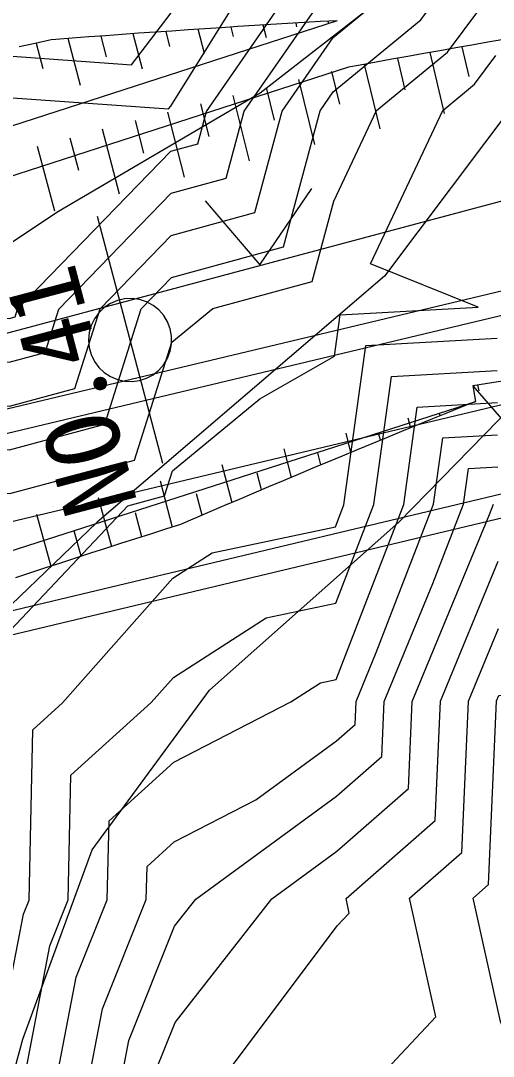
# Model space of a CAD drawing. Extents: x 42655 to 43811, y -141820 to -141156.
# Drawn here: x 43266.1 to 43280.88, y -141374.58 to -141342.18 of the extents above; entities that cross this region are included whole.
import ezdxf

# ---------------------------------------------------------------- set-up
doc = ezdxf.new("R2010")
doc.units = 0
for name, color, linetype in [('D-BMK-HTXT_1', 7, 'Continuous'), ('D-BMK_1', 7, 'Continuous'), ('D-STR-STR4_1', 7, 'Continuous'), ('D-STR-STR5_1', 7, 'Continuous'), ('D-STR_1', 7, 'Continuous'), ('ZE_HICN', 7, 'Continuous'), ('ZE_LWCN', 7, 'Continuous'), ('地形', 7, 'Continuous')]:
    doc.layers.add(name, color=color, linetype=linetype)

msp = doc.modelspace()

# ---------------------------------------------------------------- linework, layer by layer
at = {"layer": 'D-BMK-HTXT_1'}
msp.add_line((43270.542, -141356.034), (43268.499, -141348.3), dxfattribs=at)
msp.add_lwpolyline([(43268.22, -141352.167), (43268.241, -141352.399), (43268.303, -141352.624), (43268.404, -141352.834), (43268.541, -141353.022), (43268.71, -141353.183), (43268.904, -141353.312), (43269.119, -141353.403), (43269.346, -141353.455), (43269.579, -141353.466), (43269.81, -141353.434), (43270.031, -141353.362), (43270.237, -141353.252), (43270.419, -141353.107), (43270.572, -141352.931), (43270.692, -141352.731), (43270.774, -141352.513), (43270.815, -141352.284), (43270.815, -141352.05), (43270.774, -141351.821), (43270.692, -141351.603), (43270.572, -141351.403), (43270.419, -141351.227), (43270.237, -141351.082), (43270.031, -141350.972), (43269.81, -141350.9), (43269.579, -141350.868), (43269.346, -141350.879), (43269.119, -141350.931), (43268.904, -141351.022), (43268.71, -141351.151), (43268.541, -141351.312), (43268.404, -141351.5), (43268.303, -141351.71), (43268.241, -141351.935), (43268.22, -141352.167)], dxfattribs=at)
at = {"layer": 'D-BMK_1'}
msp.add_lwpolyline([(43339.878, -141340.165), (43219.961, -141368.793)], dxfattribs=at)
at = {"layer": 'D-STR-STR4_1'}
for p, q in [((43280.239, -141353.603), (43282.194, -141355.865)), ((43280.384, -141353.565), (43280.429, -141353.753))]:
    msp.add_line(p, q, dxfattribs=at)
at = {"layer": 'D-STR-STR5_1'}
for p, q in [((43272.666, -141342.375), (43272.739, -141342.666)), ((43273.782, -141342.716), (43273.682, -141342.311)), ((43274.697, -141342.25), (43274.725, -141342.364)), ((43275.724, -141342.241), (43275.713, -141342.192)), ((43267.968, -141344.198), (43267.583, -141342.733)), ((43268.6, -141342.656), (43268.768, -141343.301)), ((43269.903, -141343.695), (43269.617, -141342.582)), ((43270.633, -141342.511), (43270.753, -141342.979)), ((43271.841, -141343.201), (43271.65, -141342.442)), ((43266.582, -141342.878), (43266.792, -141343.666)), ((43279.896, -141342.993), (43280.111, -141343.922)), ((43277.879, -141343.353), (43278.111, -141344.334)), ((43279.353, -141345.078), (43278.905, -141343.169)), ((43277.336, -141345.556), (43276.853, -141343.541)), ((43275.295, -141346.051), (43274.795, -141344.011)), ((43275.82, -141343.761), (43276.068, -141344.782)), ((43273.77, -141344.264), (43274.023, -141345.283)), ((43273.257, -141346.557), (43272.746, -141344.52)), ((43271.723, -141344.778), (43271.981, -141345.796)), ((43269.678, -141345.302), (43269.941, -141346.319)), ((43271.222, -141347.073), (43270.7, -141345.039)), ((43269.189, -141347.6), (43268.657, -141345.568)), ((43267.636, -141345.837), (43267.905, -141346.852)), ((43267.159, -141348.137), (43266.616, -141346.109)), ((43280.151, -141354.134), (43280.157, -141354.159)), ((43278.207, -141354.602), (43278.284, -141354.919)), ((43279.22, -141354.538), (43279.199, -141354.452)), ((43277.349, -141355.302), (43277.292, -141355.071)), ((43276.265, -141355.08), (43276.416, -141355.688)), ((43274.325, -141355.568), (43274.553, -141356.466)), ((43275.484, -141356.076), (43275.389, -141355.699)), ((43272.388, -141356.065), (43272.696, -141357.253)), ((43273.624, -141356.858), (43273.49, -141356.337)), ((43270.453, -141356.572), (43270.837, -141358.021)), ((43271.77, -141357.65), (43271.595, -141356.984)), ((43268.521, -141357.09), (43268.937, -141358.627)), ((43266.592, -141357.616), (43267.04, -141359.241)), ((43269.887, -141358.323), (43269.687, -141357.576)), ((43267.988, -141358.933), (43267.772, -141358.142))]:
    msp.add_line(p, q, dxfattribs=at)
for points in [[(43275.994, -141342.176), (43216.96, -141361.274)], [(43275.994, -141342.176), (43275.476, -141342.205), (43274.959, -141342.235), (43274.442, -141342.265), (43273.924, -141342.297), (43273.407, -141342.328), (43272.889, -141342.361), (43272.372, -141342.394), (43271.854, -141342.428), (43271.336, -141342.463), (43270.818, -141342.498), (43270.3, -141342.534), (43269.782, -141342.57), (43269.264, -141342.608), (43268.746, -141342.645), (43268.228, -141342.684), (43267.71, -141342.723), (43267.191, -141342.763), (43267.05, -141342.774), (43266.55, -141342.885), (43266.05, -141342.996)], [(43281.211, -141342.764), (43280.711, -141342.851), (43280.21, -141342.938), (43279.71, -141343.026), (43279.209, -141343.115), (43278.709, -141343.204), (43278.209, -141343.294), (43277.709, -141343.384), (43277.209, -141343.475), (43276.709, -141343.567), (43276.345, -141343.634)], [(43276.345, -141343.634), (43217.529, -141362.662)], [(43280.32, -141354.094), (43279.855, -141354.281), (43279.391, -141354.468), (43278.928, -141354.656), (43278.465, -141354.845), (43278.002, -141355.034), (43277.539, -141355.224), (43277.077, -141355.415), (43276.615, -141355.605), (43276.153, -141355.797), (43275.692, -141355.989), (43275.231, -141356.181), (43274.77, -141356.375), (43274.31, -141356.568), (43273.85, -141356.763), (43273.39, -141356.957), (43272.931, -141357.153), (43272.472, -141357.349), (43272.013, -141357.545), (43271.555, -141357.742), (43271.097, -141357.939), (43270.626, -141358.088), (43270.156, -141358.237), (43269.685, -141358.387), (43269.215, -141358.537), (43268.745, -141358.688), (43268.276, -141358.84), (43267.806, -141358.992), (43267.337, -141359.145), (43266.868, -141359.298), (43266.399, -141359.452), (43265.93, -141359.606)]]:
    msp.add_lwpolyline(points, dxfattribs=at)
at = {"layer": 'D-STR_1'}
msp.add_line((43280.239, -141353.603), (43280.32, -141354.094), dxfattribs=at)
for points in [[(43339.6, -141336.676), (43218.633, -141365.555)], [(43339.659, -141337.424), (43218.917, -141366.249)], [(43317.868, -141337.995), (43218.254, -141364.63)], [(43340.097, -141342.907), (43221.004, -141371.338)], [(43340.157, -141343.654), (43221.288, -141372.032)], [(43340.196, -141344.153), (43280.239, -141353.603)], [(43280.321, -141354.098), (43221.668, -141372.957)]]:
    msp.add_lwpolyline(points, dxfattribs=at)
at = {"layer": 'ZE_HICN'}
for points in [[(43249.689, -141374.859), (43250.57, -141373.588), (43252.624, -141369.757), (43253.076, -141366.667), (43253.74, -141363.589), (43254.854, -141358.308), (43255.054, -141357.42), (43255.176, -141356.93), (43255.574, -141355.76), (43257.228, -141351.247), (43258.712, -141348.917), (43260.625, -141347.681), (43263.355, -141345.055), (43264.697, -141343.841), (43265.692, -141343.273), (43269.564, -141343.552), (43270.774, -141341.968), (43272.722, -141338.849), (43274.151, -141336.8), (43275.833, -141335.898), (43278.271, -141332.66), (43277.915, -141330.107), (43278.412, -141326.496), (43276.737, -141321.518)], [(43255.992, -141375.904), (43258.278, -141372.907), (43260.154, -141369.721), (43260.702, -141364.205), (43260.778, -141363.65), (43260.782, -141363.556), (43260.851, -141363.37), (43263.775, -141357.379), (43264.16, -141355.452), (43265.75, -141355.603), (43268.727, -141354.803), (43269.864, -141351.187), (43270.813, -141350.209), (43274.319, -141349.256), (43275.461, -141344.998), (43275.874, -141344.402), (43278.608, -141342.146), (43280.936, -141339.002)], [(43267.112, -141375.851), (43267.827, -141372.107), (43268.801, -141369.681), (43268.858, -141367.215), (43270.884, -141365.379), (43274.545, -141363.491), (43275.472, -141362.895), (43275.96, -141362.791), (43278.076, -141357.311), (43278.496, -141354.267), (43281.007, -141354.126)], [(43276.773, -141375.806), (43279.079, -141373.349), (43278.258, -141369.636), (43279.895, -141368.201), (43280.102, -141363.465), (43281.041, -141361.189)]]:
    msp.add_lwpolyline(points, dxfattribs=at)
at = {"layer": 'ZE_LWCN'}
for points in [[(43250.656, -141375.837), (43253.918, -141369.751), (43254.177, -141367.987), (43255.126, -141363.582), (43255.601, -141361.333), (43256.265, -141358.237), (43256.781, -141357.412), (43257.326, -141355.285), (43258.808, -141351.24), (43259.605, -141349.988), (43260.632, -141349.325), (43265.079, -141345.047), (43265.435, -141344.726), (43265.698, -141344.575), (43270.719, -141344.937), (43270.787, -141344.848), (43274.539, -141338.84), (43275.137, -141337.982), (43275.841, -141337.605), (43279.569, -141332.654), (43279.024, -141328.751), (43279.335, -141326.492), (43278.288, -141323.378)], [(43253.251, -141375.916), (43255.648, -141371.394), (43256.302, -141370.537), (43256.773, -141369.737), (43256.929, -141368.166), (43257.937, -141363.569), (43258.505, -141360.923), (43260.671, -141357.456), (43260.701, -141357.393), (43261.682, -141352.479), (43265.737, -141352.864), (43266.859, -141352.562), (43267.288, -141351.2), (43270.8, -141347.575), (43272.527, -141347.106), (43273.089, -141345.01), (43275.858, -141341.007), (43276.925, -141340.126), (43277.889, -141338.824), (43280.916, -141334.723)], [(43254.572, -141375.91), (43255.66, -141373.859), (43257.29, -141371.722), (43258.463, -141369.729), (43258.853, -141365.814), (43259.346, -141363.562), (43259.624, -141362.267), (43260.685, -141360.568), (43262.238, -141357.386), (43262.921, -141353.966), (43265.744, -141354.233), (43267.793, -141353.683), (43268.576, -141351.194), (43270.807, -141348.892), (43273.423, -141348.181), (43274.275, -141345.004), (43275.866, -141342.705), (43277.766, -141341.136), (43279.484, -141338.817), (43280.926, -141336.863)], [(43251.929, -141375.923), (43254.404, -141371.255), (43255.213, -141369.745), (43255.277, -141369.307), (43255.631, -141367.667), (43256.527, -141363.576), (43257.385, -141359.58), (43258.745, -141357.403), (43260.184, -141351.79), (43260.388, -141351.232), (43260.498, -141351.06), (43260.64, -141350.968), (43261.653, -141349.994), (43262.841, -141351.221), (43265.731, -141351.495), (43265.925, -141351.442), (43266, -141351.206), (43270.794, -141346.258), (43271.631, -141346.031), (43271.903, -141345.015), (43275.85, -141339.309)], [(43257.891, -141375.895), (43259.266, -141374.092), (43260.737, -141371.593), (43262.241, -141369.711), (43262.746, -141366.011), (43262.85, -141363.546), (43264.655, -141358.718), (43265.313, -141357.372), (43265.399, -141356.938), (43265.756, -141356.972), (43269.66, -141355.923), (43270.822, -141352.23), (43272.102, -141351.177), (43275.215, -141350.331), (43275.89, -141347.817), (43277.226, -141344.99), (43279.449, -141343.155), (43280.946, -141341.134)], [(43282.012, -141375.781), (43281.099, -141373.486), (43280.246, -141369.627), (43280.73, -141369.202), (43280.981, -141363.46), (43281.051, -141363.292), (43285.524, -141362.697), (43285.017, -141357.279), (43284.951, -141352.493), (43285.655, -141351.113), (43285.616, -141350.553), (43286.078, -141350.476), (43289.935, -141349.606), (43291.16, -141349.042), (43295.511, -141344.904), (43295.716, -141344.286), (43296.225, -141344.098), (43300.912, -141344.391), (43301.314, -141344.304), (43301.911, -141344.15), (43306.395, -141342.794), (43309.436, -141342.362), (43311.48, -141342.159), (43313.792, -141341.46)], [(43260.254, -141375.277), (43260.751, -141374.433), (43264.533, -141369.701), (43264.714, -141368.372), (43264.919, -141363.536), (43265.777, -141361.242), (43269.445, -141357.352), (43270.594, -141357.043), (43270.841, -141356.258), (43273.578, -141354.005), (43275.912, -141352.667), (43276.09, -141351.38), (43280.406, -141351.138), (43277.035, -141349.778), (43279.303, -141344.98), (43280.291, -141344.165), (43280.956, -141343.267)], [(43262.768, -141375.872), (43265.827, -141371.973), (43266.179, -141370.13), (43266.355, -141369.692), (43266.478, -141364.36), (43267.4, -141363.524), (43270.857, -141359.618), (43272.083, -141358.829), (43275.938, -141358.014), (43276.206, -141357.32), (43276.892, -141352.342), (43280.998, -141352.112)], [(43266.099, -141375.856), (43267.003, -141371.118), (43267.578, -141369.686), (43267.668, -141365.788), (43270.18, -141363.511), (43270.872, -141362.73), (43273.778, -141360.862), (43275.949, -141360.403), (43277.141, -141357.316), (43277.694, -141353.305), (43281.003, -141353.119)], [(43268.126, -141375.846), (43268.651, -141373.095), (43270.024, -141369.675), (43270.048, -141368.643), (43270.896, -141367.874), (43273.452, -141366.556), (43275.969, -141364.71), (43276.556, -141364.195), (43276.587, -141363.481), (43277.219, -141361.948), (43279.012, -141357.307), (43279.298, -141355.229), (43281.012, -141355.133)], [(43269.139, -141375.842), (43269.475, -141374.084), (43270.908, -141370.512), (43271.57, -141369.667), (43275.977, -141366.436), (43277.391, -141365.197), (43277.466, -141363.477), (43278.988, -141359.785), (43279.947, -141357.303), (43280.1, -141356.191), (43281.017, -141356.14)], [(43270.299, -141375.072), (43270.923, -141373.518), (43273.948, -141369.656), (43275.985, -141368.162), (43278.226, -141366.198), (43278.345, -141363.473), (43280.757, -141357.622), (43280.882, -141357.298)], [(43271.997, -141375.828), (43275.996, -141370.501), (43276.371, -141370.101), (43276.271, -141369.645), (43279.06, -141367.199), (43279.224, -141363.469), (43281.031, -141359.085)]]:
    msp.add_lwpolyline(points, dxfattribs=at)
at = {"layer": '地形'}
for points in [[(43294.351, -141331.831), (43287.212, -141332.387), (43284.616, -141334.517), (43283.225, -141336.926), (43283.04, -141340.261), (43281.649, -141344.615), (43277.477, -141350.173), (43268.484, -141357.862), (43265.795, -141360.456), (43262.364, -141362.216), (43259.675, -141361.29), (43259.954, -141358.047), (43259.49, -141353.323), (43267.278, -141348.135), (43273.583, -141344.43), (43277.292, -141341.558), (43278.126, -141337.667), (43277.57, -141330.534), (43278.96, -141328.403), (43282.854, -141326.551), (43290.086, -141326.643), (43295.186, -141327.014), (43294.351, -141331.831)], [(43271.87, -141347.816), (43273.578, -141349.819), (43275.197, -141347.43)], [(43288.267, -141354.855), (43285.848, -141365.022), (43286.267, -141373.121), (43283.514, -141385.454), (43279.342, -141386.896), (43276.006, -141392.479), (43271.085, -141402.146), (43263.495, -141406.646), (43258.074, -141408.063), (43249.233, -141407.397), (43252.319, -141404.646), (43256.322, -141401.063), (43260.326, -141396.896), (43262.077, -141391.23), (43264.079, -141381.71), (43266.164, -141374.043), (43268.332, -141368.119), (43272.002, -141363.119), (43277.924, -141357.869), (43283.274, -141352.393), (43288.267, -141354.855)]]:
    msp.add_lwpolyline(points, dxfattribs=at)

# ---------------------------------------------------------------- texts
at = {"layer": 'D-BMK-HTXT_1'}
msp.add_text('NO.41', height=2.3065, rotation=104.7983, dxfattribs=at).set_placement((43269.758, -141357.276))

doc.saveas('drawing.dxf')
